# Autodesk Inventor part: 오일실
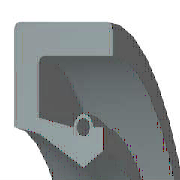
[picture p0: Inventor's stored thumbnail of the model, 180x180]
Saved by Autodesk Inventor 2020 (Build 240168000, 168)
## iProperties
Created: 2015-10
Part Number: 오일실
Material: 고무
Description: 오일-실
Document SubType Name: Modeling
Standard: KS B 2804
Designer: mdu
Standards Organization: KS
Language: ko-KR
Size Designation: S - 25 38 8
Categories: <MemberInstance><Categories><Category DisplayName="샤프트 부품" InternalName="7f7aeb1f-a693-4053-b835-cee3144e0d98" Mnemonic="SHFT"><Category DisplayName="실링" Intern
Density: 0.93 g/cm^3
Appearance: 고무 - 검은색 - 버전 1.1
IsCustomPart: 1
Author: mdu
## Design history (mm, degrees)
revolve "본체" stored, may be unused: angle "d17" = 90 deg
revolve "스프링1" stored, may be unused: angle "d18" = 90 deg
body "Solid1"
sketch "스케치1"
  geometry: L1 (0, 19)-(8, 19); L2 (8, 19)-(8, 17.75); L3 (8, 17.75)-(1.75, 17.75); L4 (0, 19)-(0, 14.6); L5 (0, 14.6)-(1.75, 14.25); L6 (1.75, 14.25)-(4.9, 12.5); L7 (4.9, 12.5)-(0, 12.5); L8 (6.3, 13.375)-(6.3, 14.6); L9 (0, 0)-(9.586, 0) reference; L10 (4.9, 12.5)-(6.3, 13.375); L11 (0, 18)-(0, -3) reference; L12 (-1.917, 0)-(11.503, 0) reference; L13 (4.2, 14.6)-(1.75, 15.09); L14 (1.75, 15.09)-(1.75, 17.75); L15 (6.3, 14.6)-(5.6, 14.6); C1 r 0.455 at (4.9, 14.6); A1 r 0.7 centre (4.9, 14.6) between (5.6, 14.6) and (4.2, 14.6)
  constraints: 26 end point, 5 horizontal alignment, 4 perpendicular, 2 centre point, 2 collinear, 2 horizontal, 2 parallel, 2 point on circle, 2 point on line, 2 vertical alignment, 1 coincident
  dimensions: "d0" = 38 diameter of L1 L9 (= SD2); "d1" = 26.75 diameter of L8.start L9 (= ABDM); "d2" = 1.25 distance of L1.end L2.end (computed from SD); "d3" = 0.91 diameter of C1 (= SPDI); "d4" = 1.4 diameter of A1 (= SPDA); "d5" = 25 diameter of L6.end L9 (= NND); "d6" = 28.5 diameter of L5.end L9 (= TKDM); "d7" = 29.2 diameter of L4.end L9 (= HLDM); "d8" = 4.9 distance from line of C1.centre L4 (= SPDST); "d9" = 6.3 distance between parallel lines of L8 L4 (= SDI); "d10" = 8 distance between parallel lines of L2 L4 (= SWDT); "d12" = 1.75 distance between parallel lines of L14 L4 (= SD)
fillet "모깎기1" dims "d11" = 0.3 (= RR)
other parameters: "SD2" = 38 [user parameter; used in 1 equation term], "SWDT" = 8 [user parameter; used in 1 equation term], "RR" = 0.3 [user parameter; used in 1 equation term], "SD" = 1.75 [user parameter; used in 2 equation terms], "NND" = 25 [user parameter; used in 1 equation term], "SPDA" = 1.4 [user parameter; used in 1 equation term], "SPDI" = 0.91 [user parameter; used in 1 equation term], "TKDM" = 28.5 [user parameter; used in 1 equation term], "HLDM" = 29.2 [user parameter; used in 1 equation term], "ABDM" = 26.75 [user parameter; used in 1 equation term], "SDI" = 6.3 [user parameter; used in 1 equation term], "SPDST" = 4.9 [user parameter; used in 1 equation term], "d13" = 0, "d14" = 0, "d15" = 0, "LAB" = 0.35 [user parameter]
